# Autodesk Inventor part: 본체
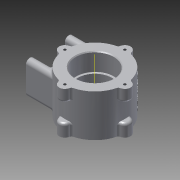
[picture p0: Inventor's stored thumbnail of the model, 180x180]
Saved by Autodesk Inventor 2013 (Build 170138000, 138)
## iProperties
Created: 2015-03
Part Number: 본체
Material: 알루미늄 6061
Document SubType Name: Modeling
Designer: cad10
Density: 2.71 g/cm^3
Mass: 450.247 g
Surface Area: 333.879 cm^2
Volume: 166.143 cm^3
Author: cad10
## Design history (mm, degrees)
sketch "스케치1"
  geometry: C1 r 37 at (0, 0); 1 further point
  constraints: 1 centre point, 1 coincident
  dimensions: "d0" = 74 diameter of C1
extrude "돌출1" new body sketch "스케치1" distance "d2" = 52; taper "d3" = 0 deg
sketch "스케치2"
  geometry: A1 r 7 centre (0, 37) between (6.969, 36.338) and (-6.969, 36.338); A2 r 7 centre (37, 0) between (36.338, -6.969) and (36.338, 6.969); A3 r 7 centre (0, -37) between (-6.969, -36.338) and (6.969, -36.338); A4 r 7 centre (-37, 0) between (-36.338, 6.969) and (-36.338, -6.969); 1 further point
  constraints: 8 point on circle, 4 centre point, 13 other
  dimensions: "d4" = 14 diameter of A4; "d6" = 14 diameter of A3; "d7" = 14 diameter of A2; "d8" = 14 diameter of A1
extrude "돌출2" join sketch "스케치2" distance "d9" = 15; taper "d10" = 0 deg
sketch "스케치4"
  geometry: A1 r 7 centre (0, 37) between (6.969, 36.338) and (-6.969, 36.338); A2 r 7 centre (0, -37) between (-6.969, -36.338) and (6.969, -36.338); A3 r 7 centre (-37, 0) between (-36.338, 6.969) and (-36.338, -6.969); A4 r 7 centre (37, 0) between (36.338, -6.969) and (36.338, 6.969); 1 further point
  constraints: 8 point on circle, 4 centre point, 13 other
  dimensions: "d14" = 14 diameter of A1; "d15" = 14 diameter of A2; "d16" = 14 diameter of A3; "d17" = 14 diameter of A4
extrude "돌출3" join sketch "스케치4" distance "d18" = 15; taper "d19" = 0 deg
sketch "스케치5"
  geometry: C1 r 23.5 at (0, 0); A1 r 37 centre (0, 0) between (-6.969, 36.338) and (-36.338, 6.969) reference
  constraints: 1 centre point, 1 coincident
  dimensions: "d20" = 47 diameter of C1
extrude "돌출4" cut sketch "스케치5" distance "d22" = 22; taper "d23" = 0 deg
sketch "스케치6"
  geometry: C1 r 23.5 at (0, 0) reference; C2 r 21 at (0, 0)
  constraints: 1 centre point, 1 coincident
  dimensions: "d24" = 42 diameter of C2
extrude "돌출5" cut sketch "스케치6" distance "d26" = 18; taper "d27" = 0 deg
sketch "스케치7"
  geometry: C1 r 23.5 at (0, 0); A1 r 37 centre (0, 0) between (6.969, -36.338) and (36.338, -6.969) reference
  constraints: 1 centre point, 1 coincident
  dimensions: "d28" = 47 diameter of C1
extrude "돌출6" cut sketch "스케치7" distance "d31" = 22; taper "d32" = 0 deg
node "작업 평면1"
sketch "스케치8"
  geometry: L1 (-29, 11)-(-29, 41); L2 (-19, 11)-(-19, 41); L3 (19, 41)-(19, 33.05); L4 (19, 33.05)-(19, 11); L5 (29, 41)-(29, 11); A1 r 5 centre (-24, 41) between (-19, 41) and (-29, 41); A2 r 5 centre (-24, 11) between (-29, 11) and (-19, 11); A3 r 5 centre (24, 41) between (29, 41) and (19, 41); A4 r 5 centre (24, 11) between (19, 11) and (29, 11)
  constraints: 10 end point, 8 point on circle, 5 tangent, 4 centre point, 1 parallel
  dimensions: "d85" = 30 distance of A2.centre A1.centre; "d88" = 30 distance of A3.centre A4.centre
extrude "돌출7" join sketch "스케치8" distance "d40" = 35; taper "d41" = 0 deg
sketch "스케치10"
  geometry: A1 r 7 centre (0, 37) between (6.969, 36.338) and (-6.969, 36.338) reference; A2 r 7 centre (-37, 0) between (-36.338, 6.969) and (-36.338, -6.969) reference; A3 r 7 centre (0, -37) between (-6.969, -36.338) and (6.969, -36.338) reference; A4 r 7 centre (37, 0) between (36.338, -6.969) and (36.338, 6.969) reference
hole "구멍1" sketch "스케치10" at (37, 0), (0, 37), (-37, 0), (0, -37) diameter "d42" = 3.242; stored, may be unused: countersink angle "d46" = 90 deg, drill point angle "d48" = 118 deg; dims "d43" = 8, "d44" = 4, "d45" = 2, "d47" = 11
sketch "스케치11"
  geometry: A1 r 7 centre (0, -37) between (-6.969, -36.338) and (6.969, -36.338) reference; A2 r 7 centre (37, 0) between (36.338, -6.969) and (36.338, 6.969) reference; A3 r 7 centre (0, 37) between (6.969, 36.338) and (-6.969, 36.338) reference; A4 r 7 centre (-37, 0) between (-36.338, 6.969) and (-36.338, -6.969) reference
hole "구멍2" sketch "스케치11" at (-37, 0), (0, -37), (37, 0), (0, 37) diameter "d49" = 3.242; stored, may be unused: countersink angle "d53" = 90 deg, drill point angle "d55" = 118 deg; dims "d50" = 8, "d51" = 4, "d52" = 2, "d54" = 11
sketch "스케치12"
  geometry: A1 r 5 centre (11, -24) between (11, -19) and (11, -29) reference; A2 r 5 centre (41, -24) between (41, -29) and (41, -19) reference; 1 further point
hole "구멍3" sketch "스케치12" at (11, -24), (41, -24) diameter "d56" = 4.134; stored, may be unused: countersink angle "d60" = 90 deg, drill point angle "d62" = 118 deg; dims "d57" = 6, "d58" = 4, "d59" = 2, "d61" = 8
sketch "스케치13"
  geometry: A1 r 5 centre (41, 24) between (41, 19) and (41, 29) reference; A2 r 5 centre (11, 24) between (11, 29) and (11, 19) reference; 1 further point
hole "구멍4" sketch "스케치13" at (11, 24), (41, 24) diameter "d63" = 4.134; stored, may be unused: countersink angle "d67" = 90 deg, drill point angle "d69" = 118 deg; dims "d64" = 6, "d65" = 4, "d66" = 2, "d68" = 8
fillet "모깎기1" dims "d70" = 3
fillet "모깎기2" dims "d71" = 3
fillet "모깎기3" dims "d72" = 3
chamfer "모따기1" distance "d73" = 1; stored, may be unused: second distance "d74" = 2, angle "d75" = 45 deg
chamfer "모따기2" distance "d76" = 1; stored, may be unused: second distance "d77" = 2, angle "d78" = 45 deg
fillet "모깎기4" dims "d79" = 0.3
node "작업 평면3"
  node "작업 평면2"
sketch "스케치14"
  geometry: 2 further points
  constraints: 1 other
  dimensions: "d92" = 0 vertical distance of point (-52, 0) point (-26, 0)
feature "엠보싱1" sketch "스케치14" dims "d14" = 14, "d90" = 0.5, "d91" = 0
node "솔리드1"
node "작업축1"
other parameters: "d33" = -56, "d34" = 24, "d36" = 5, "d37" = 5, "d38" = 15, "d39" = 15, "d80" = 45 deg, "d81" = 78.75
